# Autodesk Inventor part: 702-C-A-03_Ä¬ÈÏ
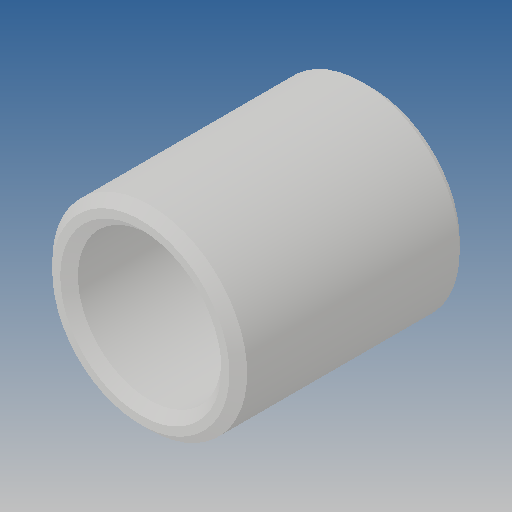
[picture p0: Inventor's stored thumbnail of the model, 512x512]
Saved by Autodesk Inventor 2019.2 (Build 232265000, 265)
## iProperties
Created: 2010-06
Part Number: 702-C-A-03_Ä¬ÈÏ
Material: Ogólny
Document SubType Name: Modeling
Designer: CADENGINEERING4
Density: 1 g/cm^3
Appearance: Domyślna
Author: CADENGINEERING4
Revision Number: ÈÎºÎ
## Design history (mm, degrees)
feature "NONE"
node "Bryła1"
